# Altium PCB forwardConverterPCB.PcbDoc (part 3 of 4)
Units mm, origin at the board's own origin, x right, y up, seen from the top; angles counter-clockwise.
Board outline 382.81 x 370.12 mm, 8 copper layers (L1, L2 (GND), L3, L4, L5(GND), L6, L7 (GND), L8), stack 1.028 mm thick; 352 components, 187 nets, 1188 pads, 1016 vias.
Unrouted connection lines stored in the file: 19.
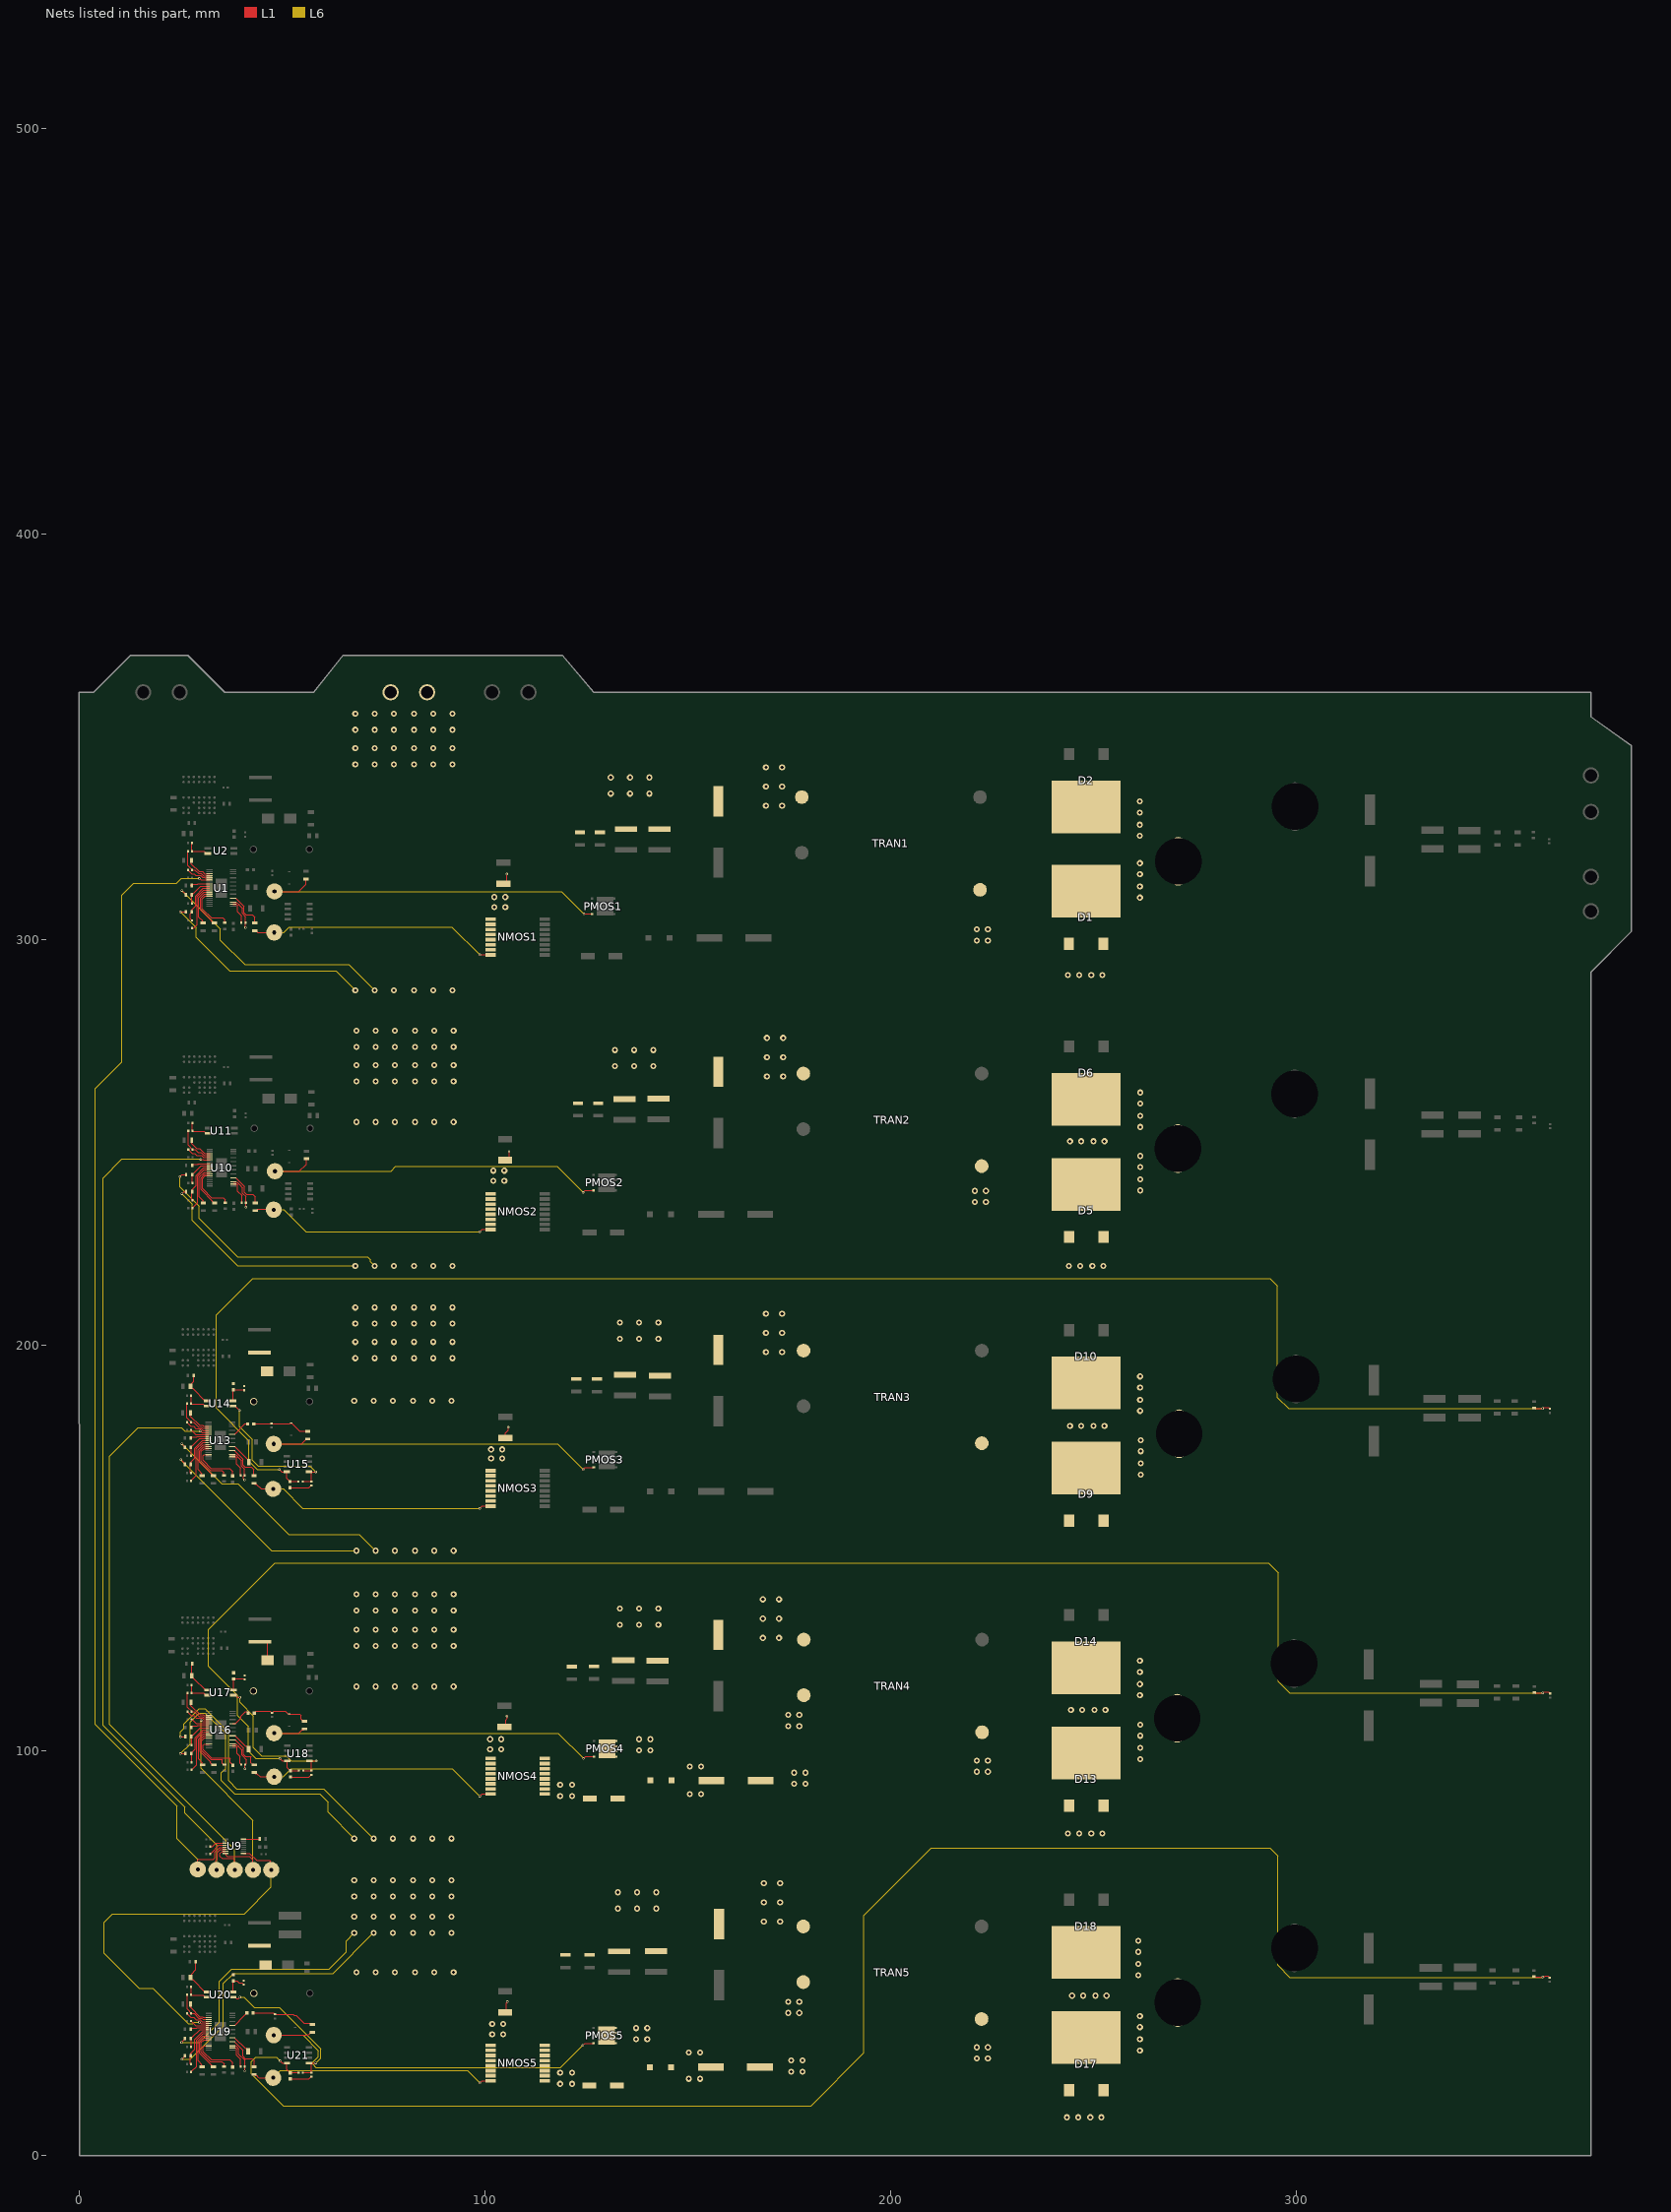
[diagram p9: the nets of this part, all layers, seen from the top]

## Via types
v1: diameter 1.5, hole 0.75, L1 to L8, tented both sides, 800 vias
v2: diameter 0.6, hole 0.3, L1 to L8, tented both sides, 216 vias

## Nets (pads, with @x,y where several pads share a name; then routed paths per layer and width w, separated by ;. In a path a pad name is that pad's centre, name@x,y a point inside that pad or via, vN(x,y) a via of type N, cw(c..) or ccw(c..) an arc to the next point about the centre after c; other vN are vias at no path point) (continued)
NetC78_2: C78.2 U13.26 | length 5.3
  L1 w0.2: U13.26@38.26,174.942 39.529,173.672 39.553,173.672 41.75,171.475 C78.2@41.75,171.125
NetC79_1: C79.1 U13.32 | length 4.2
  L1 w0.2: U13.32@38.3,178.072 40.77,180.542 C79.1@41.47,180.542
NetC79_2: C79.2 D11.2 R61.1 R62.2 | length 14.5
  L1 w0.2: R61.1@56.275,178.725 56.25,178.7 54.25,178.7 52.425,180.525 52.425,180.75 51.975,180.75 51.867,180.642 R62.2@47.32,180.642 C79.2@43.07,180.642 ; C79.2@43.07,180.642 C79.2@42.97,180.542 C79.2@43.07,180.642
NetC80_1: C80.1 R69.1 U14.3 U15.1 | length 38.4
  L1 w0.2: U14.3@37.842,184.949 38.342,184.949 38.92,184.37 38.92,184.364 39.4,183.884 v2(39.4,183.875) ; C80.1@55.02,166.342 R69.1@57.12,166.342 U15.1@57.12,168.504 ; U15.1@56.562,168.729 58.233,168.729 v2(58.24,168.722)
  L6 w0.2: v2(39.4,183.875) 39.4,179.877 42.625,176.652 42.625,171.575 44.013,170.187 56.775,170.187 v2(58.24,168.722)
NetC80_2: C80.2 C83.2 R70.1 R77.2 U15.8 | length 419.1
  L1 w0.2: v2(49.3,169.275) 49.846,168.729 U15.8@51.138,168.729 51.138,167.074 C83.2@51.92,166.292 51.97,166.342 C80.2@54.012,166.342 ; R70.1@358.683,184.503 358.833,184.353 360.878,184.353 361.1,184.575 362.261,184.575 362.383,184.453 362.383,184.403 362.533,184.253 R77.2@362.583,184.253
  L6 w0.2: v2(49.3,169.275) 43.825,169.275 41.775,171.325 41.775,176.375 33.7,184.45 33.7,207.4 42.7,216.4 293.55,216.4 295.425,214.525 295.425,187.075 298.147,184.353 v2(360.783,184.353)
NetC81_1: C81.1 R72.1 U14.4 | length 5.2
  L1 w0.2: U14.4@37.92,186.297 C81.1@37.92,188.992 R72.1@40.47,188.992
NetC81_2: C81.2 C86.2 D12.1 R72.2 R78.1
NetC82_2: C82.2 U13.7 | length 4.7
  L1 w0.2: C82.2@27.528,179.042 28.628,177.942 U13.7@31.82,177.942
NetC83_1: C83.1 R69.2 | length 5.4
  L1 w0.2: C83.1@51.92,164.792 56.52,164.792 57.07,165.342 R69.2@57.12,165.342
NetC84_2: C84.2 U13.17 | length 12.2
  L1 w0.2: U13.17@31.82,172.942 30.72,172.942 30.42,172.642 30.42,171.542 32.462,169.499 37.012,169.499 37.72,168.792 C84.2@37.72,167.692
NetC85_2: C85.2 R66.1 U14.1 | length 8.5
  L1 w0.2: C85.2@27.37,189.642 27.72,189.292 27.869,189.292 30.942,186.219 U14.1@31.442,186.219 ; C85.2@27.37,189.842 27.72,190.192 27.72,190.52 28.2,191 R66.1@28.2,192.5
NetC98_1: C98.1 R84.2
  other v1: 150.5,89.25 153.25,89.25 150.5,96 153.25,96
NetC98_2: C98.2 C99.2 NMOS4.9 NMOS4.10 NMOS4.11 NMOS4.12 NMOS4.13 NMOS4.14 NMOS4.15 NMOS4.16 TRAN4.4
  other v1: 118.5,88.75 121.5,88.75 118.5,91.5 121.5,91.5 176.25,91.75 179,91.75 176.25,94.5 179,94.5 174.75,106 177.5,106 174.75,108.75 177.5,108.75
NetC99_1: C99.1 PMOS4.5 PMOS4.6 PMOS4.7 PMOS4.8 R84.1
  other v1: 138,100 140.75,100 138,102.75 140.75,102.75
NetC101_1: C101.1 U16.32 | length 5.5
  L1 w0.2: U16.32@37.754,106.603 37.794,106.643 38.443,106.643 39.779,107.979 39.779,108.429 40.95,109.6 41.177,109.6 C101.1@41.574,109.203
NetC101_2: C101.2 D15.2 R86.1 R87.2 | length 14.6
  L1 w0.2: C101.2@43.074,109.203 43.546,109.675 46.975,109.675 47.4,109.25 47.5,109.25 47.65,109.4 47.65,109.45 47.912,109.713 50.762,109.713 51.475,109 51.984,109 54.3,109 54.6,108.7 54.6,107.775 54.9,107.475 54.9,107.45 55.15,107.2 R86.1@55.45,107.2
NetC102_2: C102.2 U16.26 | length 4
  L1 w0.2: U16.26@38.364,103.603 40.964,101.003 C102.2@41.324,101.003
NetC103_1: C103.1 R94.1 U17.3 U18.1 | length 38.4
  L1 w0.2: U17.3@37.946,113.61 38.446,113.61 38.925,113.131 39.494,113.131 v2(39.525,113.1) ; C103.1@55.124,95.003 R94.1@57.224,95.003 U18.1@57.224,97.165 ; U18.1@56.666,97.39 58.337,97.39 v2(58.344,97.383)
  L6 w0.2: v2(39.525,113.1) 39.525,111.825 42.85,108.5 42.85,100.675 44.9,98.625 50.947,98.625 52.189,97.383 v2(58.344,97.383)
NetC103_2: C103.2 C106.2 R95.1 R102.2 U18.8 | length 418.6
  L1 w0.2: v2(49.425,98.025) 50.06,97.39 U18.8@51.242,97.39 51.242,95.735 C106.2@52.024,94.953 52.074,95.003 C103.2@54.116,95.003 ; R95.1@358.75,114.3 358.9,114.15 360.917,114.15 361.167,114.4 362.3,114.4 362.45,114.25 362.45,114.2 362.6,114.05 R102.2@362.65,114.05
  L6 w0.2: v2(49.425,98.025) 43.425,98.025 41.6,99.85 41.6,105.875 38.925,108.55 38.925,113.6 31.825,120.7 31.825,129.825 48.189,146.189 293.236,146.189 295.6,143.825 295.6,117 298.45,114.15 v2(360.85,114.15)
NetC104_1: C104.1 R97.1 U17.4 | length 5.2
  L1 w0.2: U17.4@38.024,114.958 C104.1@38.024,117.653 R97.1@40.574,117.653
NetC104_2: C104.2 C109.2 D16.1 R97.2 R103.1 | length 4.3
  L1 w0.2: R103.1@46.374,122.203 C109.2@46.374,126.453
NetC105_2: C105.2 U16.7 | length 4.7
  L1 w0.2: C105.2@27.632,107.703 28.732,106.603 U16.7@31.924,106.603
NetC106_1: C106.1 R94.2 | length 5.4
  L1 w0.2: C106.1@52.024,93.453 56.624,93.453 57.174,94.003 R94.2@57.224,94.003
NetC107_2: C107.2 U16.17 | length 12.1
  L1 w0.2: U16.17@31.924,101.603 30.824,101.603 30.524,101.303 30.524,100.203 32.566,98.16 36.999,98.16 37.116,98.043 37.116,97.06 C107.2@37.824,96.353
NetC108_2: C108.2 R91.1 U17.1 | length 8.6
  L1 w0.2: R91.1@27.85,121.4 27.65,121.2 C108.2@27.65,118.4 27.65,118.2 28,117.85 28.076,117.85 31.046,114.88 U17.1@31.546,114.88
NetC121_1: C121.1 R109.2
  other v1: 150.25,19 153,19 150.25,25.5 153,25.5
NetC121_2: C121.2 C122.2 NMOS5.9 NMOS5.10 NMOS5.11 NMOS5.12 NMOS5.13 NMOS5.14 NMOS5.15 NMOS5.16 TRAN5.4
  other v1: 118.5,17.75 121.5,17.75 118.5,20.5 121.5,20.5 175.5,20.75 178.25,20.75 175.5,23.5 178.25,23.5 174.75,35.25 177.5,35.25 174.75,38 177.5,38
NetC122_1: C122.1 PMOS5.5 PMOS5.6 PMOS5.7 PMOS5.8 R109.1
  other v1: 137.25,28.75 140,28.75 137.25,31.5 140,31.5
NetC124_2: C124.2 U19.26 | length 4
  L1 w0.2: U19.26@38.273,29.121 40.873,26.521 C124.2@41.233,26.521
NetC125_1: C125.1 U19.32 | length 4.2
  L1 w0.2: U19.32@38.313,32.251 40.598,34.536 40.598,34.548 C125.1@41.275,35.225
NetC125_2: C125.2 D19.2 R111.1 R112.2 | length 15.8
  L1 w0.2: C125.2@42.775,35.225 47.825,35.225 47.95,35.1 47.95,35.05 48.1,34.9 52.675,34.9 52.925,34.65 D19.2@53.15,34.65 53.375,34.65 55.375,32.65 57.15,32.65 R111.1@57.4,32.4
NetC126_1: C126.1 R119.1 U20.3 U21.1 | length 37
  L1 w0.2: U20.3@37.855,39.128 38.355,39.128 38.683,38.8 39.212,38.8 v2(39.533,39.121) ; C126.1@55.033,20.521 R119.1@57.133,20.521 U21.1@57.133,22.683 ; U21.1@56.575,22.908 58.246,22.908 v2(58.253,22.901)
  L6 w0.2: v2(39.533,39.121) 40.529,39.121 43.05,36.6 49.25,36.6 59.425,26.425 59.425,24.073 v2(58.253,22.901)
NetC126_2: C126.2 C129.2 R120.1 R127.2 U21.8 | length 418.9
  L1 w0.2: v2(49.45,23.425) 49.967,22.908 U21.8@51.151,22.908 51.151,21.253 C129.2@51.933,20.471 51.983,20.521 C126.2@54.025,20.521 ; R120.1@358.65,44.2 358.75,44.1 v2(360.825,44.1) 360.874,44.149 361.224,44.149 361.45,44.375 362.125,44.375 362.35,44.15 362.35,44.1 362.5,43.95 R127.2@362.55,43.95
  L6 w0.2: v2(49.45,23.425) 48.6,24.275 43.425,24.275 42.4,23.25 42.4,20.175 50.225,12.35 180.375,12.35 193.4,25.375 193.4,59.275 195.2,61.075 195.2,61.1 210.075,75.975 293.514,75.975 295.525,73.964 295.525,46.975 298.45,44.05 360.775,44.05 v2(360.825,44.1)
NetC127_1: C127.1 R122.1 U20.4 | length 5.7
  L1 w0.2: U20.4@37.933,40.476 C127.1@37.933,43.171 38.889,43.171 39.389,42.671 40.104,42.671 R122.1@40.525,42.25
NetC127_2: C127.2 C132.2 D20.1 R122.2 R128.1
NetC128_2: C128.2 U19.7 | length 4.7
  L1 w0.2: C128.2@27.541,33.221 28.641,32.121 U19.7@31.833,32.121
NetC129_1: C129.1 R119.2 | length 5.4
  L1 w0.2: C129.1@51.933,18.971 56.533,18.971 57.083,19.521 R119.2@57.133,19.521
NetC130_2: C130.2 U19.17 | length 12.2
  L1 w0.2: U19.17@31.833,27.121 30.733,27.121 30.433,26.821 30.433,25.721 32.475,23.678 37.025,23.678 37.733,22.971 C130.2@37.733,21.871
NetC131_2: C131.2 R116.1 U20.1 | length 9.9
  L1 w0.2: C131.2@27.383,43.821 27.733,43.471 27.882,43.471 30.955,40.398 U20.1@31.455,40.398 ; C131.2@27.383,44.021 27.65,44.288 27.65,44.9 28.65,45.9 R116.1@28.65,47.9
NetD1_1: D1.1 D1.3 TRAN1.6
  other v1: 243.75,291.25 246.5,291.25 249.5,291.25 252.25,291.25 221.25,299.75 224,299.75 221.25,302.5 224,302.5
NetD1_4: D1.4 D2.4 L1.1
  other v1: 261.5,310.35 261.5,313.1 261.5,316.1 261.5,318.85 261.425,325.575 261.425,328.325 261.425,331.325 261.425,334.075
NetD5_1: D5.1 D5.3 TRAN2.6
  other v1: 244,219.5 246.75,219.5 249.75,219.5 252.5,219.5 220.75,235.25 223.5,235.25 220.75,238 223.5,238
NetD5_4: D5.4 D6.4 L2.1
  other v1: 261.575,238.125 261.575,240.875 261.575,243.875 261.575,246.625 244.25,250.25 247,250.25 250,250.25 252.75,250.25 261.575,253.775 261.575,256.525 261.575,259.525 261.575,262.275
NetD9_1: D9.1 D9.3 TRAN3.6
NetD9_4: D9.4 D10.4 L3.1
  other v1: 261.7,168.05 261.7,170.8 261.7,173.8 261.7,176.55 244.25,180 247,180 250,180 252.75,180 261.525,183.75 261.525,186.5 261.525,189.5 261.525,192.25
NetD13_1: D13.1 D13.3 TRAN4.6
  other v1: 243.75,79.5 246.5,79.5 249.5,79.5 252.25,79.5 221.25,94.75 224,94.75 221.25,97.5 224,97.5
NetD13_4: D13.4 D14.4 L4.1
  other v1: 261.55,97.875 261.55,100.625 261.55,103.625 261.55,106.375 244.5,110 247.25,110 250.25,110 253,110 261.5,113.6 261.5,116.35 261.5,119.35 261.5,122.1
NetD17_1: D17.1 D17.3 TRAN5.6
  other v1: 243.5,9.5 246.25,9.5 249.25,9.5 252,9.5 221.25,24 224,24 221.25,26.75 224,26.75
NetD17_4: D17.4 D18.4 L5.1
  other v1: 261.5,26 261.5,28.75 261.5,31.75 261.5,34.5 244.75,39.5 247.5,39.5 250.5,39.5 253.25,39.5 261.075,44.55 261.075,47.3 261.075,50.3 261.075,53.05
NetNMOS1_1: NMOS1.1 NMOS1.2 NMOS1.3 NMOS1.4 NMOS1.5 NMOS1.6 NMOS1.7 R9.2 R10.1 U1.22 | length 10.8
  L1 w0.2: U1.22@37.857,309.223 37.897,309.183 38.756,309.183 39.307,308.632 39.307,308.566 40.127,307.746 40.127,306.434 40.927,305.634 R9.2@40.927,304.123 40.927,302.973 v2(40.95,302.95) ; R10.1@104.577,313.773 104.625,313.773 105.325,314.473 v2(105.325,316.15)
  other v1: 102.25,308 105,308 102.25,310.5 105,310.5
NetNMOS1_8: NMOS1.8 R7.2 T2.1 | length 61.7
  L1 w0.2: R7.2@43.227,302.173 43.527,302.173 43.777,301.923 43.777,301.867 43.894,301.75 T2.1@48,301.75 ; v2(98.7,296.25) NMOS1.8@101.325,296.25
  L6 w0.2: T2.1@48,301.75 50.325,301.75 51.698,303.123 91.827,303.123 v2(98.7,296.25)
NetNMOS2_1: NMOS2.1 NMOS2.2 NMOS2.3 NMOS2.4 NMOS2.5 NMOS2.6 NMOS2.7 R42.2 R43.1 U10.22 | length 10.6
  L1 w0.2: U10.22@38,240.176 38.859,240.176 39.41,239.625 39.41,239.559 40.23,238.739 40.23,237.428 41.03,236.628 R42.2@41.03,235.116 ; v2(41.025,233.975) 41.028,233.978 41.028,235.063 R42.2@41.03,235.066 ; R43.1@104.961,245.59 105.225,245.59 105.925,246.29 v2(105.925,247.675)
  other v1: 102,240.5 104.75,240.5 102,243 104.75,243
NetNMOS2_8: NMOS2.8 R40.2 T5.1 | length 60.3
  L1 w0.2: R40.2@43.63,233.166 43.964,233.5 47.75,233.5 T5.1@47.875,233.375 ; v2(98.725,227.975) 99.25,228.5 NMOS2.8@101.325,228.5
  L6 w0.2: T5.1@47.875,233.375 50.425,233.375 55.825,227.975 v2(98.725,227.975)
NetNMOS3_1: NMOS3.1 NMOS3.2 NMOS3.3 NMOS3.4 NMOS3.5 NMOS3.6 NMOS3.7 R67.2 R68.1 U13.22 | length 11.1
  L1 w0.2: U13.22@37.69,172.902 38.549,172.902 39.1,172.351 39.1,172.285 39.92,171.465 39.92,170.154 40.72,169.353 R67.2@40.72,167.792 ; v2(40.7,166.725) 40.7,166.817 40.475,167.042 40.475,167.547 R67.2@40.72,167.792 ; R67.2@40.72,167.842 R67.2@40.72,167.792 ; R68.1@105,177.1 105,178.25 105.7,178.95 v2(105.7,179.7)
  other v1: 101.5,172 104.25,172 101.5,174.25 104.25,174.25
NetNMOS3_8: NMOS3.8 R65.2 T8.1 | length 61.1
  L1 w0.2: R65.2@43.02,165.892 43.27,165.642 43.608,165.642 44.75,164.5 T8.1@47.75,164.5 ; v2(98.725,159.725) 99.25,160.25 NMOS3.8@101.325,160.25
  L6 w0.2: T8.1@47.75,164.5 50.212,164.5 54.987,159.725 v2(98.725,159.725)
NetNMOS4_1: NMOS4.1 NMOS4.2 NMOS4.3 NMOS4.4 NMOS4.5 NMOS4.6 NMOS4.7 R92.2 R93.1 U16.22 | length 11.2
  L1 w0.2: U16.22@37.794,101.563 38.653,101.563 39.204,101.012 39.204,100.946 40.024,100.126 40.024,98.814 41.175,97.664 41.175,96.854 41.024,96.703 40.974,96.703 40.824,96.553 R92.2@40.824,96.503 ; v2(40.8,95.45) 40.812,95.462 40.812,96.441 R92.2@40.824,96.453 ; R93.1@104.8,105.8 105.075,106.075 105.075,107.55 105.542,108.017 105.542,108.183 105.502,108.223 105.502,108.423 v2(105.425,108.5)
  other v1: 101.25,100.25 104,100.25 101.25,102.75 104,102.75
NetNMOS4_8: NMOS4.8 R90.2 T11.1 | length 62.5
  L1 w0.2: R90.2@43.124,94.553 43.374,94.303 43.722,94.303 44.525,93.5 T11.1@48,93.5 ; v2(98.725,88.725) 99.25,89.25 NMOS4.8@101.325,89.25
  L6 w0.2: T11.1@48,93.5 50.25,93.5 52.253,95.503 91.947,95.503 v2(98.725,88.725)
NetNMOS5_1: NMOS5.1 NMOS5.2 NMOS5.3 NMOS5.4 NMOS5.5 NMOS5.6 NMOS5.7 R117.2 R118.1 U19.22 | length 10.9
  L1 w0.2: U19.22@37.663,27.121 37.703,27.081 38.619,27.081 39.25,26.45 39.25,25.038 40.729,23.559 40.729,20.904 v2(40.725,20.9) ; R118.1@104.95,35.4 105.275,35.725 105.275,37.667 105.5,37.892 v2(105.5,38)
  other v1: 101.75,30 104.5,30 101.75,32.5 104.5,32.5
NetNMOS5_8: NMOS5.8 R115.2 T14.1 | length 60.8
  L1 w0.2: R115.2@43.033,20.071 43.283,19.821 43.679,19.821 44,19.5 44.25,19.25 T14.1@47.75,19.25 ; v2(98.725,17.975) 99.25,18.5 NMOS5.8@101.325,18.5
  L6 w0.2: T14.1@47.75,19.25 49.521,21.021 95.679,21.021 v2(98.725,17.975)
NetPMOS1_4: PMOS1.4 R3.2 T1.1 | length 90.4
  L1 w0.2: T1.1@48.077,311.873 54.077,311.873 55.827,313.623 R3.2@55.827,314.923 ; v2(124.377,306.323) 126.357,306.323 PMOS1.4@126.362,306.318
  L6 w0.2: T1.1@48.077,311.873 118.827,311.873 v2(124.377,306.323)
NetPMOS2_4: PMOS2.4 R36.2 T4.1 | length 91.5
  L1 w0.2: T4.1@48.53,243.216 48.88,242.866 54.18,242.866 55.93,244.616 R36.2@55.93,245.916 ; v2(124.146,237.61) 124.671,238.135 PMOS2.4@126.746,238.135
  L6 w0.2: T4.1@48.18,242.866 76.801,242.866 77.985,244.05 117.706,244.05 v2(124.146,237.61)
NetPMOS3_4: PMOS3.4 R61.2 T7.1 | length 90.7
  L1 w0.2: T7.1@47.87,175.592 54.742,175.592 55.676,176.526 55.975,176.825 R61.2@56.275,176.825 ; v2(124.205,169.262) 124.73,169.787 PMOS3.4@126.805,169.787
  L6 w0.2: T7.1@47.87,175.592 117.875,175.592 v2(124.205,169.262)
NetPMOS4_4: PMOS4.4 R86.2 T10.1 | length 89.6
  L1 w0.2: T10.1@47.974,104.253 54.078,104.253 54.876,105.05 55.2,105.05 R86.2@55.45,105.3 ; v2(124.259,97.973) 124.784,98.498 PMOS4.4@126.859,98.498
  L6 w0.2: T10.1@47.974,104.253 117.979,104.253 v2(124.259,97.973)
NetPMOS5_4: PMOS5.4 R111.2 T13.1 | length 98.4
  L1 w0.2: T13.1@47.883,29.771 56.346,29.771 56.775,30.2 56.8,30.2 57.1,30.5 R111.2@57.4,30.5 ; v2(124.131,27.238) 124.656,27.763 PMOS5.4@126.731,27.763
  L6 w0.2: T13.1@47.883,29.771 55.054,29.771 58.9,25.925 58.9,24.475 57.508,23.083 57.508,22.567 58.3,21.775 118.668,21.775 v2(124.131,27.238)
NetR2_1: R2.1 U1.3 | length 6.3
  L1 w0.2: R2.1@27.577,319.523 27.577,318.673 29.5,316.75 30.3,316.75 30.827,316.223 U1.3@32.027,316.223
NetR5_1: R5.1 R17.2 U1.9 | length 7.8
  L1 w0.2: R5.1@27.527,310.973 27.477,311.023 27.477,311.123 27.777,311.123 27.777,311.273 27.877,311.373 28.027,311.373 29.877,313.223 U1.9@32.027,313.223 ; R5.1@27.677,311.023 27.727,310.973 R17.2@27.727,308.923
NetR6_1: R6.1 R13.2 U1.10 | length 11.1
  L1 w0.2: R13.2@27.727,304.723 27.727,304.773 27.577,304.923 27.527,304.923 27.3,305.15 27.3,306.355 27.417,306.473 27.477,306.473 27.677,306.673 27.677,307.373 28.627,308.323 28.627,310.788 30.521,312.683 31.26,312.683 31.987,312.683 U1.10@32.027,312.723
NetR7_1: R7.1 U1.24 | length 9.7
  L1 w0.2: U1.24@37.857,310.223 38.467,310.223 40.527,308.163 40.527,306.623 41.027,306.123 42.627,306.123 43.227,305.523 R7.1@43.227,304.073
NetR9_1: R9.1 U1.21 | length 5.9
  L1 w0.2: U1.21@37.857,308.723 37.897,308.683 38.691,308.683 38.907,308.466 38.907,306.904 39.927,305.884 R9.1@39.927,304.123
NetR15_1: R15.1 U1.5 | length 6.2
  L1 w0.2: R15.1@26.727,317.223 26.727,317.173 27.677,316.223 28.327,316.223 28.7,315.85 29.825,315.85 30.348,315.327 30.868,315.327 30.972,315.223 U1.5@32.027,315.223
NetR15_2: R15.2 R16.1 U1.4 | length 9.9
  L1 w0.2: R16.1@26.727,321.823 26.727,318.273 27.727,317.273 R15.2@27.727,317.223 28.427,317.223 29.325,316.325 29.975,316.325 30.573,315.727 31.033,315.727 31.038,315.723 U1.4@32.027,315.723
NetR16_2: R16.2 R18.2 U2.2 | length 6.2
  L1 w0.2: R18.2@27.727,323.823 R16.2@27.727,321.823 27.82,321.73 30.649,321.73 31.149,321.23 U2.2@31.649,321.23
NetR21_2: R21.2 U1.8 | length 4.8
  L1 w0.2: R21.2@27.477,313.323 27.477,313.423 27.677,313.623 29.097,313.623 29.197,313.723 U1.8@32.027,313.723
NetR22_2: R22.2 U1.14 | length 12
  L1 w0.2: U1.14@32.027,310.723 30.893,310.723 30.227,310.057 30.227,307.623 32.476,305.373 35.326,305.373 35.827,304.873 R22.2@35.827,304.123
NetR23_2: R23.2 U1.11 | length 12.3
  L1 w0.2: R23.2@27.727,302.823 27.744,302.823 27.81,302.756 27.86,302.805 28.16,302.805 29.027,303.673 29.027,310.623 30.627,312.223 30.641,312.223 U1.11@32.027,312.223
NetR24_2: R24.2 U1.12 | length 9.9
  L1 w0.2: R24.2@30.427,304.073 30.344,304.155 30.344,304.605 29.431,305.518 29.431,306.718 29.427,306.723 29.427,310.423 30.687,311.683 31.987,311.683 U1.12@32.027,311.723
NetR25_2: R25.2 U1.13 | length 10.3
  L1 w0.2: U1.13@32.027,311.223 31.987,311.183 30.787,311.183 29.827,310.223 29.827,307.373 32.677,304.523 32.677,304.323 32.927,304.073 R25.2@33.227,304.073
NetR30_2: R30.2 U9.3 | length 4.1
  L1 w0.2: R30.2@32.277,76.273 32.777,76.273 33.604,77.1 34.483,77.1 34.496,77.113 U9.3@35.987,77.113
NetR31_2: R31.2 U9.4 | length 4.6
  L1 w0.2: R31.2@32.277,74.523 32.277,74.573 32.427,74.723 32.477,74.723 34.367,76.613 U9.4@35.987,76.613
NetR32_2: R32.2 U9.16 | length 4
  L1 w0.2: U9.16@40.411,78.113 40.448,78.15 R32.2@44.4,78.15
NetR35_1: R35.1 U10.3 | length 6.3
  L1 w0.2: R35.1@27.68,250.516 27.68,249.666 28.905,248.441 29.58,248.441 30.805,247.216 U10.3@32.13,247.216
NetR38_1: R38.1 R50.2 U10.9 | length 7
  L1 w0.2: R50.2@27.83,239.916 R38.1@27.83,241.966 ; R38.1@27.98,242.366 28.13,242.366 29.98,244.216 U10.9@32.13,244.216
NetR39_1: R39.1 R46.2 U10.10 | length 9.6
  L1 w0.2: R46.2@27.63,235.716 R39.1@27.63,237.766 ; R39.1@27.78,238.016 27.78,238.366 28.73,239.316 28.73,241.781 30.624,243.676 31.363,243.676
NetR40_1: R40.1 U10.24 | length 9.1
  L1 w0.2: U10.24@38.57,241.216 40.63,239.156 40.63,237.616 41.13,237.116 42.73,237.116 43.33,236.516 R40.1@43.33,235.066
NetR42_1: R42.1 U10.21 | length 5.9
  L1 w0.2: U10.21@38,239.676 38.794,239.676 39.01,239.459 39.01,237.898 40.03,236.878 R42.1@40.03,235.116
NetR48_1: R48.1 U10.5 | length 6.1
  L1 w0.2: R48.1@26.83,248.166 27.78,247.216 28.43,247.216 28.896,246.75 30.099,246.75 30.633,246.216 U10.5@32.13,246.216
NetR48_2: R48.2 R49.1 U10.4 | length 9.9
  L1 w0.2: R49.1@26.83,252.816 26.83,249.266 R48.2@27.83,248.266 ; R48.2@27.83,248.216 28.53,248.216 29.296,247.45 30.005,247.45 30.739,246.716 U10.4@32.13,246.716
NetR49_2: R49.2 R51.2 U11.2 | length 5.5
  L1 w0.2: R49.2@27.83,252.816 R51.2@27.83,254.816 ; R49.2@27.923,252.723 30.752,252.723 U11.2@31.252,252.223
NetR54_2: R54.2 U10.8 | length 4.4
  L1 w0.2: R54.2@27.78,244.616 29.2,244.616 29.3,244.716 U10.8@32.13,244.716
NetR55_2: R55.2 U10.14 | length 12
  L1 w0.2: U10.14@32.13,241.716 30.996,241.716 30.33,241.05 30.33,238.616 32.579,236.366 35.429,236.366 35.93,235.866 R55.2@35.93,235.116
NetR56_2: R56.2 U10.11 | length 12
  L1 w0.2: R56.2@27.83,233.816 27.83,233.866 27.98,234.016 28.03,234.016 29.13,235.116 29.13,241.616 30.73,243.216 ; 30.744,243.216 U10.11@32.13,243.216
NetR57_2: R57.2 U10.12 | length 9.7
  L1 w0.2: R57.2@30.447,235.148 30.447,235.598 29.534,236.511 29.534,237.711 29.53,237.716 29.53,241.416 30.79,242.676 U10.12@32.09,242.676
NetR58_2: R58.2 U10.13 | length 9.6
  L1 w0.2: U10.13@32.09,242.176 30.89,242.176 29.93,241.216 29.93,238.366 32.78,235.516 R58.2@32.78,235.316
NetR60_1: R60.1 U13.3 | length 6.3
  L1 w0.2: R60.1@27.37,183.242 27.37,182.392 29.587,180.175 30.305,180.175 30.538,179.942 U13.3@31.82,179.942
NetR63_1: R63.1 R75.2 U13.9 | length 7
  L1 w0.2: R75.2@27.52,172.642 R63.1@27.52,174.692 ; R63.1@27.67,175.092 27.82,175.092 29.67,176.942 U13.9@31.82,176.942
NetR64_1: R64.1 R71.2 U13.10 | length 9.6
  L1 w0.2: R71.2@27.32,168.442 R64.1@27.32,170.492 ; R64.1@27.47,170.742 27.47,171.092 28.42,172.042 28.42,174.507 30.314,176.402 31.053,176.402
NetR65_1: R65.1 U13.24 | length 9.1
  L1 w0.2: U13.24@38.26,173.942 40.32,171.882 40.32,170.342 40.82,169.842 42.42,169.842 43.02,169.242 R65.1@43.02,167.792
NetR67_1: R67.1 U13.21 | length 5.9
  L1 w0.2: U13.21@37.69,172.402 38.484,172.402 38.7,172.185 38.7,170.623 39.72,169.603 R67.1@39.72,167.842
NetR73_1: R73.1 U13.5 | length 6.1
  L1 w0.2: R73.1@26.52,180.892 27.47,179.942 28.12,179.942 28.687,179.375 29.974,179.375 30.407,178.942 U13.5@31.82,178.942
NetR73_2: R73.2 R74.1 U13.4 | length 9.9
  L1 w0.2: R74.1@26.52,185.542 26.52,181.992 R73.2@27.52,180.992 ; R73.2@27.52,180.942 28.22,180.942 29.387,179.775 30.139,179.775 30.473,179.442 U13.4@31.82,179.442
NetR74_2: R74.2 R76.2 U14.2 | length 5.5
  L1 w0.2: R74.2@27.52,185.542 R76.2@27.52,187.542 ; R74.2@27.613,185.449 30.442,185.449 U14.2@30.942,184.949
NetR79_2: R79.2 U13.8 | length 4.4
  L1 w0.2: R79.2@27.47,177.342 28.89,177.342 28.99,177.442 U13.8@31.82,177.442
NetR80_2: R80.2 U13.14 | length 12
  L1 w0.2: U13.14@31.82,174.442 30.686,174.442 30.02,173.776 30.02,171.342 32.269,169.092 35.119,169.092 35.62,168.592 R80.2@35.62,167.842
NetR81_2: R81.2 U13.11 | length 12
  L1 w0.2: R81.2@27.52,166.542 27.52,166.592 27.67,166.742 27.72,166.742 28.82,167.842 28.82,174.342 30.42,175.942 ; 30.434,175.942 U13.11@31.82,175.942
NetR82_2: R82.2 U13.12 | length 9.7
  L1 w0.2: R82.2@30.137,167.874 30.137,168.324 29.224,169.237 29.224,170.437 29.22,170.442 29.22,174.142 30.48,175.402 U13.12@31.78,175.402
NetR83_2: R83.2 U13.13 | length 9.6
  L1 w0.2: U13.13@31.78,174.902 30.58,174.902 29.62,173.942 29.62,171.092 32.47,168.242 R83.2@32.47,168.042
NetR85_1: R85.1 U16.3 | length 6.3
  L1 w0.2: R85.1@27.474,111.903 27.474,111.053 29.727,108.8 30.505,108.8 30.702,108.603 U16.3@31.924,108.603
NetR88_1: R88.1 R100.2 U16.9 | length 7
  L1 w0.2: R100.2@27.624,101.303 R88.1@27.624,103.353 ; R88.1@27.774,103.753 27.924,103.753 29.774,105.603 U16.9@31.924,105.603
NetR89_1: R89.1 R96.2 U16.10 | length 9.7
  L1 w0.2: R89.1@27.574,99.203 27.624,99.153 R96.2@27.624,97.103 ; R89.1@27.574,99.403 27.624,99.403 27.774,99.553 27.774,99.603 28.524,100.353 28.524,103.168 30.418,105.063 31.157,105.063
NetR90_1: R90.1 U16.24 | length 9
  L1 w0.2: U16.24@38.364,102.603 40.424,100.543 40.424,99.003 40.924,98.503 42.183,98.503 42.3,98.385 42.3,96.975 42.572,96.703 42.874,96.703 R90.1@43.124,96.453
NetR92_1: R92.1 U16.21 | length 5.9
  L1 w0.2: U16.21@37.794,101.063 38.588,101.063 38.804,100.846 38.804,99.284 39.525,98.563 39.525,96.82 39.642,96.703 39.674,96.703 39.824,96.553 R92.1@39.824,96.503
NetR98_1: R98.1 U16.5 | length 6.1
  L1 w0.2: R98.1@26.624,109.553 27.574,108.603 28.224,108.603 28.827,108 30.174,108 30.571,107.603 U16.5@31.924,107.603
NetR98_2: R98.2 R99.1 U16.4 | length 9.9
  L1 w0.2: R99.1@26.6,114.2 26.624,114.176 26.624,110.653 R98.2@27.624,109.653 ; R98.2@27.624,109.603 28.324,109.603 29.527,108.4 30.339,108.4 30.637,108.103 U16.4@31.924,108.103
NetR99_2: R99.2 R101.2 U17.2 | length 5.6
  L1 w0.2: R101.2@27.6,116.1 27.624,116.076 27.624,114.224 R99.2@27.6,114.2 27.69,114.11 30.546,114.11 U17.2@31.046,113.61
NetR104_2: R104.2 U16.8 | length 4.4
  L1 w0.2: R104.2@27.574,106.003 28.994,106.003 29.094,106.103 U16.8@31.924,106.103
NetR105_2: R105.2 U16.14 | length 12
  L1 w0.2: U16.14@31.924,103.103 30.79,103.103 30.124,102.437 30.124,100.003 32.373,97.753 35.106,97.753 35.223,97.636 35.223,97.003 35.224,96.853 35.374,96.703 35.574,96.503 R105.2@35.724,96.503
NetR106_2: R106.2 U16.11 | length 12
  L1 w0.2: R106.2@27.624,95.203 27.624,95.253 27.774,95.403 27.824,95.403 28.924,96.503 28.924,103.003 30.524,104.603 ; 30.538,104.603 U16.11@31.924,104.603
NetR107_2: R107.2 U16.12 | length 9.7
  L1 w0.2: R107.2@30.241,96.535 30.241,96.985 29.328,97.898 29.328,99.098 29.324,99.103 29.324,102.803 30.584,104.063 U16.12@31.884,104.063
NetR108_2: R108.2 U16.13 | length 9.6
  L1 w0.2: U16.13@31.884,103.563 30.684,103.563 29.724,102.603 29.724,99.753 32.31,97.166 32.31,96.966 R108.2@32.574,96.703
NetR110_1: R110.1 U19.3 | length 6.3
  L1 w0.2: R110.1@27.383,37.421 27.383,36.571 29.629,34.325 30.304,34.325 30.508,34.121 U19.3@31.833,34.121
NetR113_1: R113.1 R125.2 U19.9 | length 7
  L1 w0.2: R125.2@27.533,26.821 R113.1@27.533,28.871 ; R113.1@27.683,29.271 27.833,29.271 29.683,31.121 U19.9@31.833,31.121
NetR114_1: R114.1 R121.2 U19.10 | length 9.6
  L1 w0.2: R121.2@27.333,22.621 R114.1@27.333,24.671 ; R114.1@27.483,24.921 27.483,25.271 28.433,26.221 28.433,28.686 30.327,30.581 31.066,30.581
NetR115_1: R115.1 U19.24 | length 9.1
  L1 w0.2: U19.24@38.273,28.121 40.333,26.061 40.333,24.521 40.833,24.021 42.433,24.021 43.033,23.421 R115.1@43.033,21.971
NetR117_1: R117.1 U19.21 | length 5.9
  L1 w0.2: U19.21@37.703,26.581 38.497,26.581 38.713,26.364 38.713,24.803 39.733,23.783 R117.1@39.733,22.021
NetR123_1: R123.1 U19.5 | length 6.1
  L1 w0.2: R123.1@26.533,35.071 27.483,34.121 28.133,34.121 28.729,33.525 29.774,33.525 30.178,33.121 U19.5@31.833,33.121
NetR123_2: R123.2 R124.1 U19.4 | length 9.9
  L1 w0.2: R124.1@26.533,39.721 26.533,36.171 R123.2@27.533,35.171 ; R123.2@27.533,35.121 28.233,35.121 29.429,33.925 30.138,33.925 30.442,33.621 U19.4@31.833,33.621
NetR124_2: R124.2 R126.2 U20.2 | length 5.5
  L1 w0.2: R124.2@27.533,39.721 R126.2@27.533,41.721 ; R124.2@27.626,39.628 30.455,39.628 U20.2@30.955,39.128
NetR129_2: R129.2 U19.8 | length 4.4
  L1 w0.2: R129.2@27.483,31.521 28.903,31.521 29.003,31.621 U19.8@31.833,31.621
NetR130_2: R130.2 U19.14 | length 12
  L1 w0.2: U19.14@31.833,28.621 30.699,28.621 30.033,27.955 30.033,25.521 32.282,23.271 35.132,23.271 35.633,22.771 R130.2@35.633,22.021
NetR131_2: R131.2 U19.11 | length 12
  L1 w0.2: R131.2@27.533,20.721 27.533,20.771 27.683,20.921 27.733,20.921 28.833,22.021 28.833,28.521 30.433,30.121 ; 30.447,30.121 U19.11@31.833,30.121
NetR132_2: R132.2 U19.12 | length 9.7
  L1 w0.2: R132.2@30.15,22.053 30.15,22.503 29.237,23.416 29.237,24.616 29.233,24.621 29.233,28.321 30.493,29.581 U19.12@31.793,29.581
NetR133_2: R133.2 U19.13 | length 9.6
  L1 w0.2: U19.13@31.793,29.081 30.593,29.081 29.633,28.121 29.633,25.271 32.483,22.421 R133.2@32.483,22.221
NetT3_1: T3.1 U1.6 U9.5 | length 288.2
  L1 w0.2: T3.1@29.15,70.65 29.15,73.033 29.267,73.15 33.024,73.15 33.422,73.548 33.422,74.922 34.563,76.063 35.937,76.063 U9.5@35.987,76.113 ; v2(29.55,315.05) 29.658,315.05 29.986,314.723 U1.6@32.027,314.723
  L6 w0.2: T3.1@29.15,70.65 29.15,73.1 24.075,78.175 24.075,86.247 3.9,106.422 3.9,263.225 10.475,269.8 10.475,311 13.405,313.93 23.956,313.93 25.076,315.05 v2(29.55,315.05)
NetT6_1: T6.1 U9.6 U10.6 | length 217.5
  L1 w0.2: v2(29.9,245.825) 29.909,245.816 30.5,245.816 30.6,245.716 U10.6@32.13,245.716 ; T6.1@33.777,70.523 33.65,70.65 33.65,72.9 33.933,73.183 33.933,74.867 34.678,75.613 U9.6@35.987,75.613
  L6 w0.2: v2(29.9,245.825) 29.85,245.875 10.475,245.875 5.775,241.175 5.775,106.175 25.938,86.012 25.938,84.487 33.825,76.6 33.825,70.571 T6.1@33.777,70.523
NetT9_1: T9.1 U9.7 U13.6 | length 151.4
  L1 w0.2: v2(29.725,178.775) 29.833,178.775 30.167,178.442 U13.6@31.82,178.442 ; U9.7@35.987,75.113 35.937,75.063 35.15,75.063 34.65,74.562 34.65,73.9 35.15,73.4 37.9,73.4 38.277,73.023 T9.1@38.277,70.523
  L6 w0.2: v2(29.725,178.775) 25.926,178.775 25.082,179.619 14.469,179.619 7.425,172.575 7.425,106.425 38.277,75.573 T9.1@38.277,70.523
NetT12_1: T12.1 U9.8 U16.6 | length 54.5
  L1 w0.2: v2(29.925,107.4) 30.033,107.4 30.331,107.103 U16.6@31.924,107.103 ; U9.8@35.987,74.613 36.1,74.613 36.15,74.563 36.15,74.15 36.4,73.9 41.9,73.9 42.777,73.023 T12.1@42.777,70.523
  L6 w0.2: v2(29.925,107.4) 29.925,95.626 42.777,82.774 T12.1@42.777,70.523
NetT15_1: T15.1 U9.9 U19.6 | length 99.6
  L1 w0.2: v2(29.525,32.925) 29.633,32.925 29.938,32.621 U19.6@31.833,32.621 ; U9.9@40.411,74.613 41.937,74.613 43.65,72.9 46.9,72.9 47.15,72.65 47.15,70.65 T15.1@47.277,70.523
  L6 w0.2: v2(29.525,32.925) 28.272,32.925 27.972,32.625 26.828,32.625 18.102,41.351 14.724,41.351 6.075,50 6.075,57.625 8.15,59.7 40.65,59.7 47.277,66.327 T15.1@47.277,70.523
Vin: C1.1 C3.2 C4.2 C5.2 C6.2 C42.1 C44.2 C45.2 C46.2 C47.2 C65.1 C67.2 C68.2 C69.2 C70.2 C88.1 C90.2 C91.2 C92.2 C93.2 C111.1 C113.2 C114.2 C115.2 C116.2 J1.1 J2.1 R5.2 R6.2 R38.2 R39.2 R63.2 R64.2 R88.2 R89.2 R113.2 R114.2 TRAN1.1 TRAN2.1 TRAN3.1 TRAN4.1 TRAN5.1 | length 622.4
  L1 w0.2: v2(24.75,241.55) 25.2,242 26.264,242 R38.2@26.28,242.016 ; v2(24.827,306.873) 26.127,306.873 R6.2@26.177,306.823 ; v2(24.894,99.187) 26.058,99.187 R89.2@26.074,99.203 ; v2(24.894,103.387) 26.058,103.387 R88.2@26.074,103.403 ; v2(25,171.7) 25,171.662 25.97,170.692 R64.2@25.97,170.542 ; v2(25.175,27.95) 25.175,27.963 25.983,28.771 R113.2@25.983,28.921 ; v2(25.225,23.8) 25.225,23.813 25.983,24.571 R114.2@25.983,24.721 ; v2(25.225,237.325) 25.7,237.8 26.264,237.8 R39.2@26.28,237.816 ; v2(25.225,312.125) 26.177,311.173 R5.2@26.177,311.023 ; v2(25.25,175.65) 25.25,175.612 25.97,174.892 R63.2@25.97,174.742
  L6 w0.2: v2(24.75,241.55) 24.75,239 29.5,234.25 29.5,231.25 39,221.75 71,221.75 71.751,220.999 71.751,220.499 v1(72.75,219.5) ; v2(24.827,306.873) 28.75,302.95 28.75,300.5 37,292.25 63.25,292.25 v1(68,287.5) ; v2(24.894,99.187) 27.25,101.543 27.25,107 29.5,109.25 31,109.25 36,104.25 36,95.5 35,94.5 35,92.5 38.25,89.25 59.25,89.25 61.25,87.25 61.25,84.75 v1(67.75,78.25) ; v2(24.894,103.387) 24.894,104.57 25.75,105.426 25.75,106.5 29.5,110.25 31,110.25 36.75,104.5 36.75,92.5 38.75,90.5 60.25,90.5 v1(72.5,78.25) ; v2(25,171.7) 25,171.651 47.401,149.25 v1(68.25,149.25) ; v2(25.175,27.95) 29.45,27.95 34.5,33 34.5,43 37.5,46 61.5,46 65.75,50.25 65.75,53 v1(67.75,55) ; v2(25.225,23.8) 27.3,23.8 35.5,32 35.5,42.5 38,45 62.5,45 v1(72.5,55) ; v2(25.225,237.325) 27.776,234.774 27.776,230.724 39,219.5 v1(68,219.5) ; v2(25.225,312.125) 34.75,302.6 34.75,299.867 40.809,293.808 66.442,293.808 v1(72.75,287.5) ; v2(25.25,175.65) 35.085,165.815 39.062,165.815 51.626,153.25 69,153.25 v1(73,149.25)
  other v1: 68.25,45.25 73,45.25 77.75,45.25 82.75,45.25 87.5,45.25 92.25,45.25 77.25,55 82.25,55 87,55 91.75,55 168.75,57.75 172.75,57.75 67.75,59 72.5,59 77.25,59 82.25,59 87,59 91.75,59 132.75,61 137.5,61 142.25,61 168.75,62.5 172.75,62.5 67.75,64 72.5,64 77.25,64 82.25,64 87,64 91.75,64 132.75,65 137.5,65 142.25,65 168.75,67.25 172.75,67.25 67.75,68 72.5,68 77.25,68 82.25,68 87,68 91.75,68 77.25,78.25 82.25,78.25 87,78.25 91.75,78.25 68.25,115.75 73,115.75 77.75,115.75 82.75,115.75 87.5,115.75 92.25,115.75 68.25,125.75 73,125.75 77.75,125.75 82.75,125.75 87.5,125.75 92.25,125.75 168.5,127.75 172.5,127.75 68.25,129.75 73,129.75 77.75,129.75 82.75,129.75 87.5,129.75 92.25,129.75 133.25,131 138,131 142.75,131 168.5,132.5 172.5,132.5 68.25,134.5 73,134.5 77.75,134.5 82.75,134.5 87.5,134.5 92.25,134.5 133.25,135 138,135 142.75,135 168.5,137.25 172.5,137.25 68.25,138.5 73,138.5 77.75,138.5 82.75,138.5 87.5,138.5 92.25,138.5 77.75,149.25 82.75,149.25 87.5,149.25 92.25,149.25 67.75,186.25 72.5,186.25 77.25,186.25 82.25,186.25 87,186.25 91.75,186.25 68,196.75 72.75,196.75 77.5,196.75 82.5,196.75 87.25,196.75 92,196.75 169.25,198.25 173.25,198.25 68,200.75 72.75,200.75 77.5,200.75 82.5,200.75 87.25,200.75 92,200.75 133.25,201.5 138,201.5 142.75,201.5 169.25,203 173.25,203 68,205.25 72.75,205.25 77.5,205.25 82.5,205.25 87.25,205.25 92,205.25 133.25,205.5 138,205.5 142.75,205.5 169.25,207.75 173.25,207.75 68,209.25 72.75,209.25 77.5,209.25 82.5,209.25 87.25,209.25 92,209.25 77.5,219.5 82.5,219.5 87.25,219.5 92,219.5 68.25,255 73,255 77.75,255 82.75,255 87.5,255 92.25,255 68.25,265 73,265 77.75,265 82.75,265 87.5,265 92.25,265 169.5,266.25 173.5,266.25 132,268.75 136.75,268.75 141.5,268.75 68.25,269 73,269 77.75,269 82.75,269 87.5,269 92.25,269 169.5,271 173.5,271 132,272.75 136.75,272.75 141.5,272.75 68.25,273.5 73,273.5 77.75,273.5 82.75,273.5 87.5,273.5 92.25,273.5 169.5,275.75 173.5,275.75 68.25,277.5 73,277.5 77.75,277.5 82.75,277.5 87.5,277.5 92.25,277.5 77.5,287.5 82.5,287.5 87.25,287.5 92,287.5 169.25,333 173.25,333 131,336 135.75,336 140.5,336 169.25,337.75 173.25,337.75 131,340 135.75,340 140.5,340 169.25,342.5 173.25,342.5 68,343.25 72.75,343.25 77.5,343.25 82.5,343.25 87.25,343.25 92,343.25 68,347.25 72.75,347.25 77.5,347.25 82.5,347.25 87.25,347.25 92,347.25 68,351.75 72.75,351.75 77.5,351.75 82.5,351.75 87.25,351.75 92,351.75 68,355.75 72.75,355.75 77.5,355.75 82.5,355.75 87.25,355.75 92,355.75
pads on no net: U1.1 U1.2 U1.15 U1.16 U1.30 U1.34 U1.36 U1.37 U3.2 U3.4 U3.7 U9.10 U9.11 U9.12 U10.1 U10.2 U10.15 U10.16 U10.30 U10.34 U10.36 U10.37 U12.2 U12.4 U12.7 U13.1 U13.2 U13.15 U13.16 U13.30 U13.34 U13.36 U13.37 U15.2 U15.4 U15.7 U16.1 U16.2 U16.15 U16.16 U16.30 U16.34 U16.36 U16.37 U18.2 U18.4 U18.7 U19.1 U19.2 U19.15 U19.16 U19.30 U19.34 U19.36 U19.37 U21.2 U21.4 U21.7
copper on no net: | length 2.4
  L1 w0.2: v2(25.294,517.362) 26.458,517.362 26.474,517.378 ; v2(25.397,448.355) 26.561,448.355 26.577,448.371
  other v1: 244.25,148.75 247,148.75 250,148.75 252.75,148.75 221.25,165 224,165 221.25,167.75 224,167.75

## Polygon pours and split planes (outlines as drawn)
GND on L1 "GND_L01_P284" (solid, pour order 284): 97.769,323.287 98.769,324.287 168.919,324.287 169.919,323.287 169.919,319.237 166.019,314.287 127.6,314.3 126.909,313.609 126.909,307.267 126.649,306.907 122.886,306.907 114.636,317.287 98.769,317.287 97.769,318.287
NetC2_1 on L1 "L1-NetC2_1" (solid, pour order 288): 296.196,327.875 298.2,325.871 373.696,325.871 375.7,327.875 375.7,345.429 365.425,355.704 298.2,355.704 296.196,353.7
Vin on L1 "L1-No Net" (solid, pour order 293): 49 vertices, not listed, extent 65.009,5.292 186.969,364.5
GND on L1 "L1-NetC2_1" (solid, pour order 337): 296.696,23.661 281.161,23.418 275.28,17.699 275.28,2.245 277.475,0.55 364.35,0.55 365.95,2.15 365.95,41.25 363.946,43.254 298.7,43.254 296.696,41.25
+PH2 on L1 "L1-+PH2 1" (solid, pour order 353): 363.446,255.621 363.452,255.621 365.456,257.625 365.456,321.998 363.452,324.002 363.448,324.002 298.202,324.002 296.198,321.998 296.198,305.998 296.197,273.626 296.196,273.625 296.196,257.625 298.2,255.621
+PH3 on L1 "L1-+PH3" (solid, pour order 356): 346.016,185.496 363.452,185.371 365.456,187.375 365.456,251.748 363.452,253.752 298.202,253.752 296.198,251.748 296.198,235.748 296.198,203.502 296.196,203.5 296.196,187.5 298.2,185.496
+PH4 on L1 "L1-+PH4" (solid, pour order 357): 346.834,115.242 363.702,115.121 365.706,117.125 365.706,181.498 363.702,183.502 347.702,183.502 347.7,183.5 298.2,183.5 296.196,181.496 296.196,165.496 296.196,117.373 298.327,115.242
+PH5 on L1 "L1-+PH5" (solid, pour order 358): 296.525,47.421 298.704,45.242 363.696,45.242 365.7,47.246 365.7,111.186 363.696,113.191 363.641,113.191 363.573,113.258 298.327,113.258 296.525,111.456
GND on L1 "GND_L01_P396" (solid, pour order 396): 98.115,46.4 99.115,47.4 169.4,47.4 170.265,46.4 170.265,40.583 166.365,35.633 127.946,35.646 127.254,34.954 127.254,28.613 126.994,28.253 123.232,28.253 114.982,38.633 99.115,38.633 98.115,39.633
GND on L1 "GND_L01_P398" (solid, pour order 398): 98.115,117.15 99.115,118.15 169.4,118.15 170.265,117.15 170.265,111.333 166.365,106.383 127.946,106.396 127.254,105.704 127.254,99.363 126.994,99.003 123.232,99.003 114.982,109.383 99.115,109.383 98.115,110.383
GND on L1 "GND_L01_P400" (solid, pour order 400): 98.115,188.15 99.115,189.15 169.4,189.15 170.265,188.15 170.265,182.333 166.365,177.383 127.946,177.396 127.254,176.704 127.254,170.875 127.025,170.6 122.75,170.6 114.982,180.383 99.115,180.383 98.115,181.383
GND on L1 "GND_L01_P402" (solid, pour order 402): 98.365,256.15 99.365,257.15 169.65,257.15 170.515,256.15 170.515,250.333 166.615,245.383 128.196,245.396 127.504,244.704 127.504,238.854 127.15,238.5 123.1,238.5 115.232,248.383 99.365,248.383 98.365,249.383
NetD17_4 on L1 "NETD17_4_L01_P1124" (solid, pour order 1124): 236.138,56.388 238.15,58.4 271.624,58.4 274.099,56.388 274.099,23.695 271.624,21.394 237.844,21.394 236.138,23.1
NetD13_4 on L1 "NETD13_4_L01_P1123" (solid, pour order 1123): 235.888,126.588 237.9,128.6 271.374,128.6 273.849,126.588 273.849,93.895 271.374,91.594 237.594,91.594 235.888,93.3
NetD9_4 on L1 "NETD9_4_L01_P1122" (solid, pour order 1122): 235.938,196.788 237.95,198.8 271.424,198.8 273.899,196.788 273.899,164.095 271.424,161.794 237.644,161.794 235.938,163.5
NetD5_4 on L1 "NETD5_4_L01_P1121" (solid, pour order 1121): 236.139,266.919 238.151,268.931 271.625,268.931 274.1,266.919 274.1,234.226 271.625,231.925 237.845,231.925 236.139,233.631
NetC121_2 on L1 "L1-NetC121_2" (solid, pour order 1087): 19 vertices, not listed, extent 111.208,8.068 182.283,45.418
NetC98_2 on L1 "L1-NetC98_2" (solid, pour order 1085): 19 vertices, not listed, extent 111.336,78.803 182.411,116.153
NetC75_2 on L1 "L1-NetC75_2" (solid, pour order 1083): 19 vertices, not listed, extent 111.282,150.092 182.357,187.442
NetC52_2 on L1 "L1-NetC52_2" (solid, pour order 1081): 19 vertices, not listed, extent 111.223,218.44 182.298,255.79
NetC11_2 on L1 "L1-NetC11_2" (solid, pour order 1079): 19 vertices, not listed, extent 110.837,286.625 181.912,323.975
NetC12_1 on L1 "NETC12_1_L01_P278" (solid, pour order 278): 127.273,311.375 127.873,312.125 134.3,312.125 141.05,312.125 141.8,311.375 141.8,303.125 141.8,294.375 141.3,293.875 130.3,293.875 129.8,294.375 129.8,296.375 129.8,300.625 127.273,304.102
NetD1_4 on L1 "NETD1_4_L01_P294" (solid, pour order 294): 235.914,339.094 237.926,341.106 271.4,341.106 273.875,339.094 273.875,306.401 271.4,304.1 237.62,304.1 235.914,305.806
+12V on L1 "L1-+12V" (solid, pour order 376): 51 vertices, not listed, extent 5.95,5.231 27.7,364.5
NetNMOS1_1 on L1 "NETNMOS1_1_L01_P264" (solid, pour order 264): 97.95,313.75 99.2,315 109.2,315 110.2,313.75 106.688,303.744 106.688,297.794 105.888,296.994 98.962,296.994 97.95,298.006
+3.3V on L1 "+3.3V_L01_P420" (solid, pour order 420): 31.625,59.375 31.975,59.725 33.625,59.725 33.95,59.325 33.95,57.75 33.625,57.425 31.975,57.425 31.625,57.775
NetC33_2 on L1 "NETC33_2_L01_P419" (solid, pour order 419): 31.225,132.875 31.575,133.225 33.225,133.225 33.55,132.825 33.55,131.25 33.225,130.925 31.575,130.925 31.225,131.275
NetC27_2 on L1 "NETC27_2_L01_P418" (solid, pour order 418): 31.325,203.975 31.675,204.325 33.325,204.325 33.65,203.925 33.65,202.35 33.325,202.025 31.675,202.025 31.325,202.375
NetC31_2 on L1 "NETC31_2_L01_P417" (solid, pour order 417): 31.625,271.275 31.975,271.625 33.625,271.625 33.95,271.225 33.95,269.65 33.625,269.325 31.975,269.325 31.625,269.675
GND on L1 "GND_L01_P416" (solid, pour order 416): 25.35,59.35 25.65,59.65 31.05,59.65 31.35,59.35 31.35,57.75 31.05,57.45 25.65,57.45 25.35,57.75
+PH5 on L1 "+PH5_L01_P415" (solid, pour order 415): 24.95,132.85 25.25,133.15 30.65,133.15 30.95,132.85 30.95,131.25 30.65,130.95 25.25,130.95 24.95,131.25
+PH4 on L1 "+PH4_L01_P414" (solid, pour order 414): 25.05,204.05 25.35,204.35 30.75,204.35 31.05,204.05 31.05,202.45 30.75,202.15 25.35,202.15 25.05,202.45
+PH3 on L1 "+PH3_L01_P413" (solid, pour order 413): 25.35,271.25 25.65,271.55 31.05,271.55 31.35,271.25 31.35,269.65 31.05,269.35 25.65,269.35 25.35,269.65
GND on L1 "GND_L01_P412" (solid, pour order 412): 21 vertices, not listed, extent 25.25,49.75 34.05,54.75
GND on L1 "GND_L01_P411" (solid, pour order 411): 21 vertices, not listed, extent 24.75,123.25 33.55,128.25
GND on L1 "GND_L01_P410" (solid, pour order 410): 21 vertices, not listed, extent 24.95,194.35 33.75,199.35
GND on L1 "GND_L01_P409" (solid, pour order 409): 21 vertices, not listed, extent 25.25,261.65 34.05,266.65
GND on L1 "GND_L01_P408" (solid, pour order 408): 21 vertices, not listed, extent 25.1,330.6 33.9,335.6
+PH2 on L1 "+PH2_L01_P407" (solid, pour order 407): 25.2,340.3 25.5,340.6 30.9,340.6 31.2,340.3 31.2,338.7 30.9,338.4 25.5,338.4 25.2,338.7
NetC17_2 on L1 "NETC17_2_L01_P406" (solid, pour order 406): 18 vertices, not listed, extent 36.7,320.9 48,335.3
NetC58_2 on L1 "NETC58_2_L01_P405" (solid, pour order 405): 18 vertices, not listed, extent 36.8,251.8 48.1,266.2
NetC81_2 on L1 "NETC81_2_L01_P404" (solid, pour order 404): 18 vertices, not listed, extent 36.6,184.5 47.9,198.9
NetC104_2 on L1 "NETC104_2_L01_P403" (solid, pour order 403): 18 vertices, not listed, extent 36.6,113.2 47.9,127.6
NetC122_1 on L1 "NETC122_1_L01_P395" (solid, pour order 395): 127.669,32.818 128.269,33.568 134.696,33.568 141.446,33.568 142.196,32.818 142.196,24.568 142.196,15.818 141.696,15.318 130.696,15.318 130.196,15.818 130.196,17.818 130.196,22.068 127.669,25.545
NetC99_1 on L1 "NETC99_1_L01_P392" (solid, pour order 392): 127.797,103.553 128.397,104.303 134.824,104.303 141.574,104.303 142.324,103.553 142.324,95.303 142.324,86.553 141.824,86.053 130.824,86.053 130.324,86.553 130.324,88.553 130.324,92.803 127.797,96.28
NetC98_1 on L1 "NETC98_1_L01_P391" (solid, pour order 391): 143.324,97.053 144.074,97.803 159.574,97.803 160.324,97.053 160.324,88.053 159.574,87.303 144.074,87.303 143.324,88.053
NetC76_1 on L1 "NETC76_1_L01_P389" (solid, pour order 389): 127.743,174.842 128.343,175.592 134.77,175.592 141.52,175.592 142.27,174.842 142.27,166.592 142.27,157.842 141.77,157.342 130.77,157.342 130.27,157.842 130.27,159.842 130.27,164.092 127.743,167.569
NetC75_1 on L1 "NETC75_1_L01_P388" (solid, pour order 388): 143.27,168.342 144.02,169.092 159.52,169.092 160.27,168.342 160.27,159.342 159.52,158.592 144.02,158.592 143.27,159.342
NetC53_1 on L1 "NETC53_1_L01_P386" (solid, pour order 386): 127.684,243.19 128.284,243.94 134.711,243.94 141.461,243.94 142.211,243.19 142.211,234.94 142.211,226.19 141.711,225.69 130.711,225.69 130.211,226.19 130.211,228.19 130.211,232.44 127.684,235.917
NetC127_2 on L1 "NETC127_2_L01_P381" (solid, pour order 381): 20 vertices, not listed, extent 36.6,38.7 47.9,53.1
NetC52_1 on L1 "NETC52_1_L01_P359" (solid, pour order 359): 143.211,236.69 143.961,237.44 159.461,237.44 160.211,236.69 160.211,227.69 159.461,226.94 143.961,226.94 143.211,227.69
NetNMOS5_1 on L1 "NETNMOS5_1_L01_P319" (solid, pour order 319): 97.7,36 98.95,37.25 108.95,37.25 109.95,36 106.438,25.994 106.438,20.044 105.638,19.244 98.713,19.244 97.7,20.256
NetNMOS4_1 on L1 "NETNMOS4_1_L01_P318" (solid, pour order 318): 97.7,106.75 98.95,108 108.95,108 109.95,106.75 106.438,96.744 106.438,90.794 105.638,89.994 98.713,89.994 97.7,91.006
NetNMOS3_1 on L1 "NETNMOS3_1_L01_P317" (solid, pour order 317): 97.7,177.75 98.95,179 108.95,179 109.95,177.75 106.438,167.744 106.438,161.794 105.638,160.994 98.713,160.994 97.7,162.006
